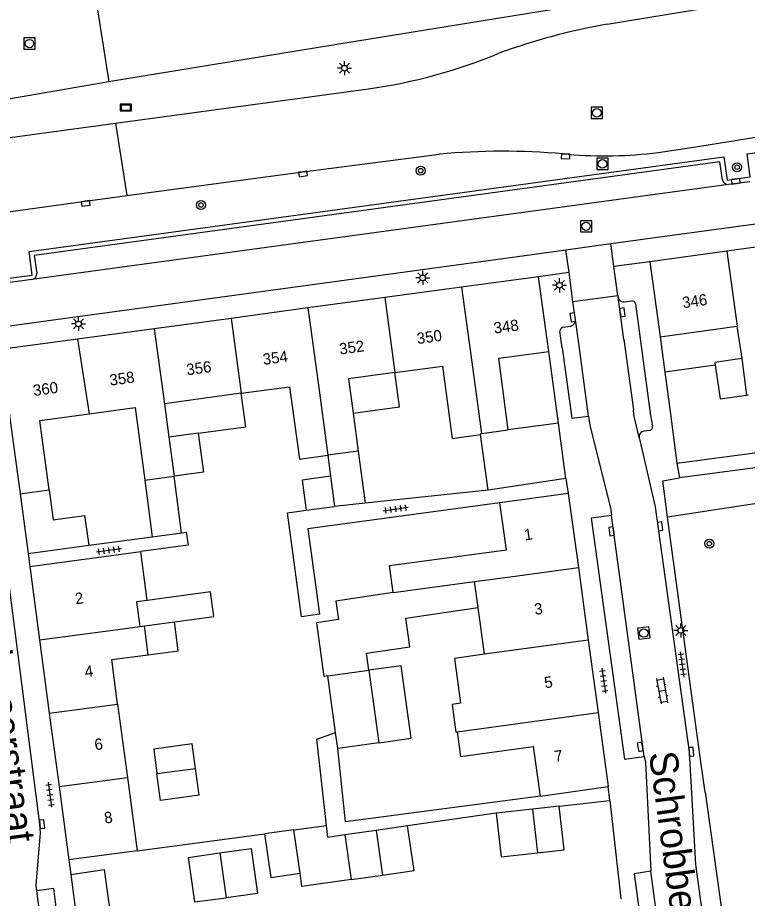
# Model space of a CAD drawing. Extents: x 132999 to 136000, y 398499 to 400501.
# Drawn here: x 133166.8 to 133231.7, y 398560.9 to 398639.2 of the extents above; entities that cross this region are included whole.
import ezdxf

# ---------------------------------------------------------------- set-up
doc = ezdxf.new("R2010")
doc.units = 0
for name, color, linetype in [('gg-afsc-erfafscheiding', 7, 'Continuous'), ('gg-afsc-hekwerk', 7, 'Continuous'), ('gg-afsc-muur', 7, 'Continuous'), ('gg-anno-huisnummerreeks BGT', 7, 'Continuous'), ('gg-anno-openbare ruimte label', 7, 'Continuous'), ('gg-bbg-bijgebouw', 7, 'Continuous'), ('gg-bbg-gedigitaliseerde bebouwing', 7, 'Continuous'), ('gg-bbg-gedigitaliseerde bijgebouw', 7, 'Continuous'), ('gg-bbg-hoofdgebouw', 7, 'Continuous'), ('gg-bbg-luifel en loopbrug', 7, 'Continuous'), ('gg-bbg-tussenscheiding', 7, 'Continuous'), ('gg-knt-verharding', 7, 'Continuous'), ('gg-knt-verharding nz', 7, 'Continuous'), ('gt-grn-groengrens', 7, 'Continuous'), ('gt-grn-weggrens', 7, 'Continuous'), ('gt-symb-boom', 7, 'Continuous'), ('gt-symb-klinker verharding', 7, 'Continuous'), ('gt-symb-kolk', 7, 'Continuous'), ('gt-symb-lichtmast', 7, 'Continuous'), ('gt-symb-reclamebord', 7, 'Continuous'), ('gt-symb-rioolschacht', 7, 'Continuous'), ('gt-symb-tegel verharding', 7, 'Continuous')]:
    doc.layers.add(name, color=color, linetype=linetype)

# ---------------------------------------------------------------- blocks, each defined once
blk = doc.blocks.new('gt0-RS')
at = {"layer": 'gt-symb-rioolschacht'}
blk.add_lwpolyline([(-0.5, -0.5), (0.5, -0.5), (0.5, 0.5), (-0.5, 0.5)], close=True, dxfattribs=at)
blk.add_circle((0, 0), 0.375, dxfattribs=at)
blk = doc.blocks.new('gt0-LMAST')
at = {"layer": 'gt-symb-lichtmast'}
for p, q in [((-0.182, 0.173), (-0.447, 0.438)), ((-0.005, 0.246), (-0.005, 0.621)), ((0.172, 0.173), (0.437, 0.438)), ((-0.255, -0.004), (-0.63, -0.004)), ((-0.182, -0.181), (-0.447, -0.446)), ((-0.005, -0.254), (-0.005, -0.629)), ((0.437, -0.446), (0.172, -0.181)), ((0.245, -0.004), (0.62, -0.004))]:
    blk.add_line(p, q, dxfattribs=at)
blk.add_circle((-0.005, -0.004), 0.25, dxfattribs=at)
blk = doc.blocks.new('gt0-KOLK')
at = {"layer": 'gt-symb-kolk'}
blk.add_lwpolyline([(0, 0), (0.375, 0), (0.375, 0.4), (-0.375, 0.4), (-0.375, 0), (0, 0)], dxfattribs=at)
blk = doc.blocks.new('gt0-RBORD')
at = {"layer": 'gt-symb-reclamebord'}
blk.add_lwpolyline([(-0.5, 0.295), (-0.5, -0.295), (0.5, -0.295), (0.5, 0.295), (-0.5, 0.295)], dxfattribs=at)
blk.add_lwpolyline([(-0.417, -0.212), (0.417, -0.212), (0.417, 0.212), (-0.417, 0.212)], close=True, dxfattribs=at)
blk = doc.blocks.new('gt0-BOOM')
at = {"layer": 'gt-symb-boom'}
for radius in [0.4, 0.2]:
    blk.add_circle((0, 0), radius, dxfattribs=at)
blk = doc.blocks.new('gt0-TEG1')
at = {"layer": 'gt-symb-tegel verharding'}
for p, q in [((-1.125, 0), (1.125, 0)), ((-0.9, -0.25), (-0.9, 0.25)), ((-0.45, -0.25), (-0.45, 0.25)), ((0, -0.25), (0, 0.25)), ((0.45, -0.25), (0.45, 0.25)), ((0.9, -0.25), (0.9, 0.25))]:
    blk.add_line(p, q, dxfattribs=at)
blk = doc.blocks.new('gt0-KL1')
at = {"layer": 'gt-symb-klinker verharding'}
for p, q in [((-1.15, 0.3), (1.15, 0.3)), ((-1, -0.3), (-1, 0.3)), ((-0.5, 0.3), (-0.5, 0.45)), ((0, -0.3), (0, 0.3)), ((0.5, 0.3), (0.5, 0.45)), ((1, -0.3), (1, 0.3)), ((-1.15, -0.3), (1.15, -0.3)), ((-0.5, -0.45), (-0.5, -0.3)), ((0.5, -0.45), (0.5, -0.3))]:
    blk.add_line(p, q, dxfattribs=at)

msp = doc.modelspace()

# ---------------------------------------------------------------- linework, layer by layer
at = {"layer": 'gg-afsc-erfafscheiding'}
for p, q in [((133225.4, 398599.565), (133232.545, 398600.532)), ((133239.524, 398600.141), (133225.611, 398598.262)), ((133225.611, 398598.262), (133225.6, 398598.261)), ((133208.613, 398597.188), (133197.682, 398596.025)), ((133174.689, 398592.486), (133178.743, 398593.035)), ((133195.939, 398567.682), (133195.231, 398574.206)), ((133213.258, 398569.968), (133195.939, 398567.682)), ((133209.332, 398568.432), (133201.452, 398567.303)), ((133177.396, 398565.099), (133188.728, 398566.606))]:
    msp.add_line(p, q, dxfattribs=at)
for points in [[(133209.663, 398596.05), (133192.585, 398593.748), (133193.615, 398586.138), (133192.005, 398585.92), (133190.753, 398595.165), (133192.44, 398595.394)], [(133181.35, 398593.388), (133181.768, 398593.445), (133181.926, 398592.273), (133177.722, 398591.704)], [(133194.246, 398567.34), (133193.374, 398575.039), (133195.038, 398575.631)]]:
    msp.add_lwpolyline(points, dxfattribs=at)
at = {"layer": 'gg-afsc-hekwerk'}
for p, q in [((133227.5, 398573.213), (133224.568, 398594.787)), ((133227.895, 398570.303), (133227.5, 398573.213)), ((133227.895, 398570.303), (133230.484, 398551.813))]:
    msp.add_line(p, q, dxfattribs=at)
msp.add_lwpolyline([(133224.568, 398594.787), (133224.129, 398598.014), (133225.6, 398598.261)], dxfattribs=at)
at = {"layer": 'gg-afsc-muur'}
for p, q in [((133214.866, 398603.126), (133214.02, 398609.501)), ((133224.329, 398607.658), (133224.781, 398604.178)), ((133224.781, 398604.178), (133225.4, 398599.565)), ((133173.09, 398592.269), (133174.689, 398592.486)), ((133214.923, 398569.06), (133219.43, 398569.565)), ((133219.43, 398569.565), (133220.42, 398560.811))]:
    msp.add_line(p, q, dxfattribs=at)
at = {"layer": 'gg-bbg-bijgebouw'}
for p, q in [((133228.794, 398608.287), (133229.249, 398605.312)), ((133214.866, 398603.126), (133210.398, 398602.533)), ((133215.528, 398598.198), (133214.866, 398603.126)), ((133215.528, 398598.198), (133208.613, 398597.188)), ((133212.547, 398568.793), (133209.332, 398568.432)), ((133214.923, 398569.06), (133212.547, 398568.793)), ((133171.494, 398562.979), (133172.004, 398559.146))]:
    msp.add_line(p, q, dxfattribs=at)
for points in [[(133231.155, 398608.873), (133228.759, 398608.519), (133228.794, 398608.287)], [(133209.332, 398568.432), (133209.768, 398564.546), (133212.983, 398564.907)]]:
    msp.add_lwpolyline(points, dxfattribs=at)
at = {"layer": 'gg-bbg-gedigitaliseerde bebouwing'}
for p, q in [((133186.656, 398605.79), (133179.824, 398604.863)), ((133231.571, 398605.632), (133231.751, 398605.657)), ((133179.824, 398604.863), (133180.218, 398601.903)), ((133196.598, 398604.026), (133197.056, 398600.645)), ((133191.825, 398599.937), (133194.344, 398600.278)), ((133178.073, 398598.073), (133180.681, 398598.419)), ((133166.99, 398596.848), (133169.564, 398597.197)), ((133167.85, 398590.391), (133177.722, 398591.704)), ((133178.298, 398587.371), (133177.722, 398591.704)), ((133208.285, 398582.576), (133207.722, 398586.734)), ((133175.661, 398578.149), (133176.528, 398571.624)), ((133176.528, 398571.624), (133177.396, 398565.099)), ((133177.396, 398565.099), (133171.32, 398564.291))]:
    msp.add_line(p, q, dxfattribs=at)
for points in [[(133200.319, 398607.643), (133204.536, 398608.215), (133205.407, 398601.779), (133207.936, 398602.121)], [(133200.319, 398607.643), (133196.184, 398607.081), (133196.598, 398604.026)], [(133186.656, 398605.79), (133190.954, 398606.373), (133191.825, 398599.937)], [(133169.564, 398597.197), (133168.729, 398603.359), (133173.134, 398603.956)], [(133173.134, 398603.956), (133177.215, 398604.523), (133178.073, 398598.073)], [(133200.149, 398588.07), (133199.825, 398590.463), (133210.236, 398591.873), (133209.663, 398596.05)], [(133175.661, 398578.149), (133175.135, 398582.105), (133178.387, 398582.538)], [(133208.285, 398582.576), (133205.604, 398582.204), (133206.157, 398578.223), (133205.402, 398578.119), (133205.743, 398575.66), (133205.855, 398575.677)], [(133205.855, 398575.677), (133206.159, 398573.484), (133212.623, 398574.377)], [(133213.258, 398569.968), (133212.656, 398574.381), (133212.623, 398574.377)]]:
    msp.add_lwpolyline(points, dxfattribs=at)
at = {"layer": 'gg-bbg-gedigitaliseerde bijgebouw'}
for p, q in [((133229.249, 398605.312), (133231.571, 398605.632)), ((133182.827, 398602.25), (133180.218, 398601.903)), ((133208.613, 398597.188), (133207.936, 398602.121)), ((133194.344, 398600.278), (133194.597, 398598.409)), ((133197.056, 398600.645), (133197.682, 398596.025)), ((133194.597, 398598.409), (133194.959, 398595.735)), ((133197.682, 398596.025), (133194.959, 398595.735)), ((133195.038, 398575.631), (133194.359, 398580.648)), ((133198.005, 398581.153), (133198.896, 398574.713)), ((133195.231, 398574.206), (133195.038, 398575.631)), ((133198.896, 398574.713), (133195.231, 398574.206)), ((133182.906, 398570.03), (133182.587, 398572.43)), ((133201.452, 398567.303), (133198.654, 398566.903)), ((133191.332, 398566.952), (133188.728, 398566.606)), ((133191.884, 398563.099), (133191.332, 398566.952)), ((133198.654, 398566.903), (133195.856, 398566.502)), ((133195.856, 398566.502), (133196.424, 398562.535)), ((133181.939, 398564.509), (133184.737, 398564.909)), ((133184.737, 398564.909), (133187.535, 398565.31)), ((133171.494, 398562.979), (133174.464, 398563.438)), ((133196.424, 398562.535), (133199.222, 398562.936))]:
    msp.add_line(p, q, dxfattribs=at)
for points in [[(133182.827, 398602.25), (133183.289, 398598.766), (133180.681, 398598.419)], [(133180.711, 398585.461), (133184.213, 398585.927), (133183.921, 398588.119), (133178.298, 398587.371)], [(133200.149, 398588.07), (133195.068, 398587.289), (133195.316, 398585.671), (133193.383, 398585.374)], [(133198.005, 398581.153), (133197.794, 398582.676), (133201.649, 398583.226), (133201.301, 398585.796), (133207.722, 398586.734)], [(133178.387, 398582.538), (133181.053, 398582.892), (133180.711, 398585.461)], [(133194.359, 398580.648), (133194.029, 398580.602), (133193.383, 398585.374)], [(133182.587, 398572.43), (133182.298, 398574.6), (133178.869, 398574.143), (133179.157, 398571.974)], [(133182.906, 398570.03), (133179.476, 398569.574), (133179.157, 398571.974)], [(133212.983, 398564.907), (133215.359, 398565.174), (133214.923, 398569.06)], [(133199.222, 398562.936), (133202.02, 398563.337), (133201.452, 398567.303)], [(133188.728, 398566.606), (133189.284, 398562.726), (133191.884, 398563.099)], [(133187.535, 398565.31), (133188.111, 398561.287), (133185.309, 398560.915)], [(133181.939, 398564.509), (133182.507, 398560.542), (133185.309, 398560.915)], [(133174.464, 398563.438), (133174.983, 398559.542), (133172.004, 398559.146)]]:
    msp.add_lwpolyline(points, dxfattribs=at)
at = {"layer": 'gg-bbg-hoofdgebouw'}
for p, q in [((133236.665, 398619.374), (133229.834, 398618.433)), ((133229.834, 398618.433), (133223, 398617.491)), ((133223, 398617.491), (133223.92, 398610.801)), ((133213.08, 398616.161), (133206.248, 398615.235)), ((133214.02, 398609.501), (133213.08, 398616.161)), ((133206.248, 398615.235), (133199.416, 398614.31)), ((133199.416, 398614.31), (133192.584, 398613.384)), ((133192.584, 398613.384), (133185.752, 398612.459)), ((133185.752, 398612.459), (133178.92, 398611.533)), ((133223.92, 398610.801), (133230.728, 398611.76)), ((133230.728, 398611.76), (133231.155, 398608.873)), ((133178.92, 398611.533), (133172.088, 398610.607)), ((133172.088, 398610.607), (133165.25, 398609.681)), ((133165.25, 398609.681), (133166.99, 398596.848)), ((133215.73, 398596.88), (133209.663, 398596.05)), ((133215.73, 398596.88), (133216.63, 398590.29)), ((133167.85, 398590.391), (133168.718, 398583.866)), ((133216.63, 398590.29), (133217.51, 398583.842)), ((133168.718, 398583.866), (133169.585, 398577.341)), ((133217.51, 398583.842), (133218.388, 398577.41)), ((133169.585, 398577.341), (133170.453, 398570.816)), ((133218.388, 398577.41), (133219.29, 398570.801)), ((133170.453, 398570.816), (133171.32, 398564.291)), ((133213.258, 398569.968), (133219.29, 398570.801))]:
    msp.add_line(p, q, dxfattribs=at)
msp.add_lwpolyline([(133210.398, 398602.533), (133209.552, 398608.908), (133214.02, 398609.501)], dxfattribs=at)
at = {"layer": 'gg-bbg-luifel en loopbrug'}
for p, q in [((133223.92, 398610.801), (133224.329, 398607.658)), ((133228.794, 398608.287), (133224.329, 398607.658)), ((133181.35, 398593.388), (133180.681, 398598.419)), ((133178.073, 398598.073), (133178.743, 398593.035)), ((133166.99, 398596.848), (133167.71, 398591.541)), ((133192.44, 398595.394), (133194.959, 398595.735)), ((133178.743, 398593.035), (133181.35, 398593.388)), ((133167.71, 398591.541), (133173.09, 398592.269)), ((133191.332, 398566.952), (133194.246, 398567.34))]:
    msp.add_line(p, q, dxfattribs=at)
for points in [[(133196.598, 398604.026), (133200.733, 398604.588), (133200.319, 398607.643)], [(133182.827, 398602.25), (133187.058, 398602.813), (133186.656, 398605.79)], [(133194.597, 398598.409), (133192.078, 398598.068), (133192.44, 398595.394)], [(133169.564, 398597.197), (133169.923, 398594.546), (133172.73, 398594.927), (133173.09, 398592.269)], [(133198.896, 398574.713), (133201.771, 398575.111), (133200.88, 398581.551), (133198.005, 398581.153)], [(133195.856, 398566.502), (133194.365, 398566.288), (133194.246, 398567.34)], [(133196.424, 398562.535), (133192.054, 398561.909), (133191.884, 398563.099)]]:
    msp.add_lwpolyline(points, dxfattribs=at)
at = {"layer": 'gg-bbg-tussenscheiding'}
for p, q in [((133206.248, 398615.235), (133207.151, 398608.569)), ((133199.416, 398614.31), (133200.319, 398607.643)), ((133192.584, 398613.384), (133193.488, 398606.716)), ((133185.752, 398612.459), (133186.656, 398605.79)), ((133178.92, 398611.533), (133179.824, 398604.863)), ((133172.088, 398610.607), (133173.134, 398603.956)), ((133231.155, 398608.873), (133231.571, 398605.632)), ((133207.151, 398608.569), (133208.012, 398602.205)), ((133193.488, 398606.716), (133194.344, 398600.278)), ((133208.012, 398602.205), (133210.398, 398602.533)), ((133180.218, 398601.903), (133180.681, 398598.419)), ((133197.056, 398600.645), (133194.344, 398600.278)), ((133200.149, 398588.07), (133207.41, 398589.04)), ((133207.722, 398586.734), (133207.41, 398589.04)), ((133177.631, 398585.052), (133178.046, 398585.107)), ((133178.046, 398585.107), (133180.711, 398585.461)), ((133178.387, 398582.538), (133178.046, 398585.107)), ((133168.718, 398583.866), (133174.793, 398584.674)), ((133174.793, 398584.674), (133177.631, 398585.052)), ((133217.51, 398583.842), (133208.285, 398582.576)), ((133194.359, 398580.648), (133198.005, 398581.153)), ((133169.585, 398577.341), (133175.661, 398578.149)), ((133205.855, 398575.677), (133218.388, 398577.41)), ((133179.157, 398571.974), (133182.587, 398572.43)), ((133170.453, 398570.816), (133176.528, 398571.624)), ((133212.547, 398568.793), (133212.983, 398564.907)), ((133198.654, 398566.903), (133199.222, 398562.936)), ((133184.737, 398564.909), (133185.309, 398560.915))]:
    msp.add_line(p, q, dxfattribs=at)
for points in [[(133229.834, 398618.433), (133230.754, 398611.764), (133230.728, 398611.76)], [(133208.012, 398602.205), (133207.926, 398602.193), (133207.936, 398602.121)], [(133207.41, 398589.04), (133210.558, 398589.461), (133216.63, 398590.29)], [(133178.298, 398587.371), (133177.34, 398587.244), (133177.631, 398585.052)]]:
    msp.add_lwpolyline(points, dxfattribs=at)
at = {"layer": 'gg-knt-verharding'}
for p, q in [((133219.189, 398638.634), (133245.219, 398642.943)), ((133175.468, 398629.825), (133197.967, 398632.88)), ((133215.274, 398627.086), (133215.736, 398627.054)), ((133229.992, 398624.361), (133168.037, 398615.899)), ((133219.526, 398619.111), (133262.283, 398624.966)), ((133231.89, 398624.612), (133229.992, 398624.361)), ((133215.529, 398618.563), (133219.526, 398619.111)), ((133168.037, 398615.899), (133162.241, 398615.138)), ((133216.139, 398613.965), (133220.139, 398614.496)), ((133220.139, 398614.496), (133220.157, 398614.344)), ((133216.367, 398612.336), (133216.139, 398613.965)), ((133220.712, 398613.921), (133221.395, 398614.006)), ((133215.265, 398611.677), (133215.954, 398611.774)), ((133215.204, 398609.821), (133214.987, 398611.327)), ((133222.981, 398602.483), (133222.45, 398602.424)), ((133222.044, 398601.85), (133223.451, 398595.68)), ((133215.528, 398598.198), (133215.73, 398596.88)), ((133167.71, 398591.541), (133167.85, 398590.391))]:
    msp.add_line(p, q, dxfattribs=at)
for points in [[(133244.913, 398644.871), (133230.172, 398642.496), (133194.972, 398636.784), (133176.134, 398633.702), (133174.884, 398633.487)], [(133223.718, 398627.205), (133226.687, 398627.653), (133234.811, 398628.974), (133253.034, 398631.976), (133263.989, 398633.764)], [(133174.884, 398633.487), (133161.488, 398631.18), (133160.734, 398631.06)], [(133102.511, 398609.465), (133113.145, 398610.953), (133123.789, 398612.407), (133124.075, 398610.324), (133130.011, 398611.121), (133129.71, 398613.205), (133142.103, 398614.9), (133142.386, 398612.828), (133148.306, 398613.635), (133148.02, 398615.716), (133161.853, 398617.594), (133162.14, 398615.537), (133168.069, 398616.307), (133167.791, 398618.397), (133195.414, 398622.174), (133229.558, 398626.811), (133229.851, 398624.756), (133231.92, 398625.045), (133231.654, 398627.101), (133261.342, 398631.158), (133261.665, 398628.664)], [(133161.239, 398627.888), (133164.325, 398628.312), (133175.468, 398629.825)], [(133176.493, 398623.384), (133192.118, 398625.499), (133204.271, 398627.06)], [(133229.449, 398624.789), (133229.208, 398626.368), (133168.245, 398618.048), (133168.467, 398616.467)], [(133162.266, 398621.435), (133172.803, 398622.884), (133176.493, 398623.384)], [(133162.1, 398611.273), (133212.511, 398618.15), (133215.529, 398618.563)], [(133221.717, 398613.759), (133223.052, 398603.828), (133223.211, 398602.863)], [(133215.204, 398609.821), (133216.062, 398603.578), (133217.54, 398603.755)], [(133217.54, 398603.755), (133217.655, 398602.963), (133219.508, 398595.46), (133219.572, 398594.934)], [(133223.451, 398595.68), (133226.474, 398573.9), (133227.035, 398563.877), (133228.491, 398553.283)], [(133168.486, 398561.534), (133168.429, 398562.029), (133168.809, 398566.695), (133168.742, 398567.452), (133166.048, 398588.548), (133164.318, 398594.201), (133164.22, 398594.876)], [(133219.572, 398594.934), (133217.773, 398594.673), (133220.728, 398573.235), (133222.495, 398573.478)], [(133222.495, 398573.478), (133222.601, 398572.971), (133223.083, 398563.284)], [(133223.083, 398563.284), (133221.584, 398563.049), (133222.964, 398552.935), (133224.471, 398553.17)], [(133170.015, 398549.442), (133171.507, 398549.648), (133169.986, 398561.738), (133168.486, 398561.534)]]:
    msp.add_lwpolyline(points, dxfattribs=at)
for centre, radius, start, end in [((133230.481, 398577.371), 62.295, 100.44325, 109.62028), ((133191.578, 398679.058), 46.618, 277.87687, 292.69273), ((133209.916, 398566.177), 61.144, 84.97316, 95.29762), ((133218.999, 398665.589), 38.673, 265.15933, 277.00821), ((133229.971, 398624.893), 0.532, 191.23932, 272.26936), ((133167.959, 398616.405), 0.512, 278.79376, 6.95172), ((133220.667, 398614.437), 0.518, 190.35524, 275.0182), ((133221.41, 398613.692), 0.315, 12.34303, 92.67473), ((133215.865, 398612.272), 0.506, 280.10218, 7.27532), ((133215.32, 398611.348), 0.333, 99.42315, 183.65763), ((133222.526, 398601.94), 0.49, 98.94044, 190.51471), ((133222.942, 398602.766), 0.286, 277.78883, 19.84123)]:
    msp.add_arc(centre, radius, start, end, dxfattribs=at)
at = {"layer": 'gg-knt-verharding nz'}
for p, q in [((133220.663, 398610.579), (133220.157, 398614.344)), ((133216.694, 398610.022), (133216.367, 398612.336)), ((133220.663, 398610.579), (133221.539, 398604.328)), ((133217.54, 398603.755), (133216.694, 398610.022)), ((133222.495, 398573.478), (133219.572, 398594.934)), ((133170.015, 398549.442), (133168.486, 398561.534))]:
    msp.add_line(p, q, dxfattribs=at)
for points in [[(133222.044, 398601.85), (133221.578, 398603.868), (133221.539, 398604.328)], [(133224.471, 398553.17), (133224.348, 398553.786), (133223.083, 398563.284)]]:
    msp.add_lwpolyline(points, dxfattribs=at)
at = {"layer": 'gt-grn-groengrens'}
msp.add_line((133241.296, 398597.331), (133224.568, 398594.787), dxfattribs=at)
at = {"layer": 'gt-grn-weggrens'}
for p, q in [((133173.864, 398639.895), (133174.884, 398633.487)), ((133175.468, 398629.825), (133176.493, 398623.384)), ((133219.798, 398617.062), (133219.526, 398619.111)), ((133215.799, 398616.525), (133215.529, 398618.563)), ((133223, 398617.491), (133219.798, 398617.062)), ((133215.799, 398616.525), (133213.08, 398616.161)), ((133216.139, 398613.965), (133215.799, 398616.525)), ((133220.139, 398614.496), (133219.798, 398617.062)), ((133225.4, 398599.565), (133225.611, 398598.262)), ((133219.43, 398569.565), (133219.29, 398570.801)), ((133171.32, 398564.291), (133171.494, 398562.979))]:
    msp.add_line(p, q, dxfattribs=at)

# ---------------------------------------------------------------- block references
at = {"layer": 'gt-symb-boom'}
for p in [(133202.61, 398625.598), (133230.745, 398625.899), (133183.073, 398622.537), (133228.272, 398592.421)]:
    msp.add_blockref('gt0-BOOM', p, dxfattribs=at)
at = {"layer": 'gt-symb-klinker verharding', "rotation": -79.69002960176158}
msp.add_blockref('gt0-KL1', (133224.071, 398579.341), dxfattribs=at)
at = {"layer": 'gt-symb-kolk'}
for p, rotation in [((133215.505, 398627.07), 177.27138596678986), ((133192.118, 398625.499), -172.29443831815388), ((133230.659, 398624.454), 7.331208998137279), ((133172.803, 398622.884), -172.1723225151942), ((133220.345, 398612.967), -82.40855614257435), ((133216.335, 398612.566), 97.9668929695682), ((133219.786, 398593.531), 97.99231392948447), ((133223.71, 398593.92), -82.18581914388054), ((133222.323, 398574.382), 100.78161673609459), ((133226.474, 398573.9), -87.13473427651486), ((133168.742, 398567.452), -84.95083353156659)]:
    msp.add_blockref('gt0-KOLK', p, dxfattribs=dict(at, rotation=rotation))
at = {"layer": 'gt-symb-lichtmast'}
for p in [(133195.841, 398634.709), (133202.796, 398616.059), (133214.956, 398615.401), (133172.183, 398611.962), (133225.749, 398584.705)]:
    msp.add_blockref('gt0-LMAST', p, dxfattribs=at)
at = {"layer": 'gt-symb-reclamebord'}
msp.add_blockref('gt0-RBORD', (133176.394, 398631.202), dxfattribs=at)
at = {"layer": 'gt-symb-rioolschacht'}
for p in [(133167.814, 398636.898), (133218.275, 398630.738), (133218.776, 398626.202), (133217.32, 398620.643)]:
    msp.add_blockref('gt0-RS', p, dxfattribs=at)
at = {"layer": 'gt-symb-rioolschacht', "rotation": 97.0681400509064}
msp.add_blockref('gt0-RS', (133222.449, 398584.465), dxfattribs=at)
at = {"layer": 'gt-symb-tegel verharding'}
for p, rotation in [((133200.396, 398595.496), 7.814180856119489), ((133174.894, 398591.829), 7.587069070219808), ((133225.876, 398581.667), 97.75742578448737), ((133218.878, 398580.219), -82.24257421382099), ((133169.643, 398570.085), -82.41293093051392)]:
    msp.add_blockref('gt0-TEG1', p, dxfattribs=dict(at, rotation=rotation))

# ---------------------------------------------------------------- texts
at = {"layer": 'gg-anno-huisnummerreeks BGT'}
for s, rotation, p in [('346', 7.9, (133225.935, 398613.352)), ('348', 7.7, (133209.171, 398611.091)), ('350', 7.7, (133202.337, 398610.165)), ('352', 7.7, (133195.439, 398609.231)), ('354', 7.7, (133188.637, 398608.309)), ('356', 7.7, (133181.843, 398607.389)), ('358', 7.7, (133175.011, 398606.463)), ('360', 7.7, (133168.211, 398605.542)), ('1', 7.8, (133211.872, 398592.695)), ('2', 7.6, (133171.942, 398587.019)), ('3', 7.8, (133212.776, 398586.071)), ('4', 7.6, (133172.805, 398580.525)), ('5', 7.8, (133213.666, 398579.552)), ('6', 7.6, (133173.668, 398574.037)), ('7', 7.8, (133214.561, 398572.991)), ('8', 7.6, (133174.536, 398567.512))]:
    msp.add_text(s, height=1, rotation=rotation, dxfattribs=at).set_placement(p)
at = {"layer": 'gg-anno-openbare ruimte label'}
for s, rotation, p in [('Plesserstraat', 277.4, (133163.399, 398585.057)), ('Schrobbelaarstraat', 277.8, (133222.899, 398573.787))]:
    msp.add_text(s, height=2.5, rotation=rotation, dxfattribs=at).set_placement(p)

doc.saveas('drawing.dxf')
